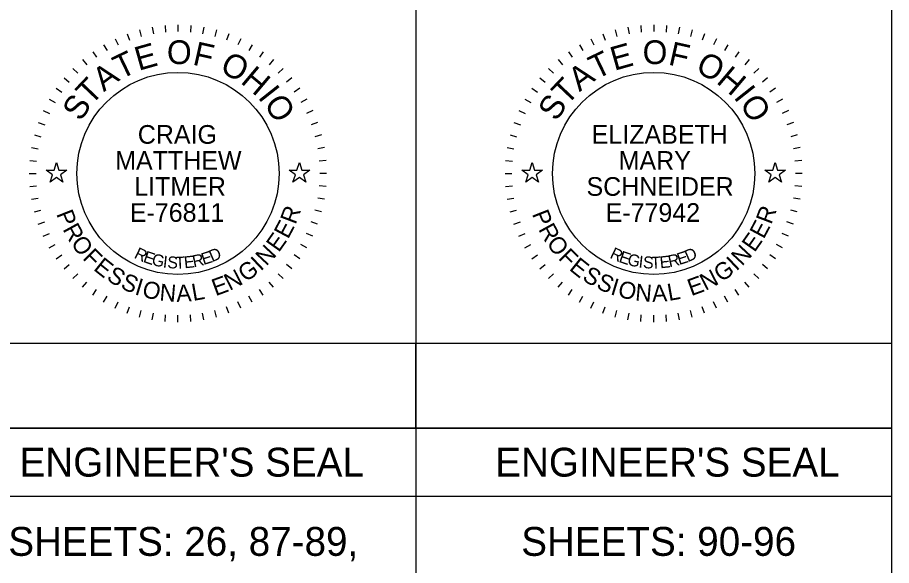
# Model space of a CAD drawing. Extents: x -21.9 to 47.3, y 14.1 to 48.7.
# Drawn here: x 24.06 to 29.2, y 29.92 to 33.15 of the extents above; entities that cross this region are included whole.
import ezdxf

# ---------------------------------------------------------------- set-up
doc = ezdxf.new("R2010")
doc.units = 0
for name, color, linetype in [('SH_Data', 7, 'Continuous'), ('SH_Seal', 7, 'Continuous'), ('SH_Text', 7, 'Continuous')]:
    doc.layers.add(name, color=color, linetype=linetype)

msp = doc.modelspace()

# ---------------------------------------------------------------- linework, layer by layer
at = {"layer": 'SH_Data'}
for p, q in [((26.4, 34.2334), (26.4, 30.7334)), ((29.2, 34.2334), (29.2, 30.7334)), ((23.6, 30.7334), (26.4, 30.7334)), ((23.6, 30.7334), (26.4, 30.7334)), ((26.4, 30.7334), (29.2, 30.7334)), ((26.4, 30.7334), (26.4, 27.2334)), ((26.4, 30.7334), (29.2, 30.7334)), ((29.2, 30.7334), (29.2, 27.2334)), ((23.6, 30.3334), (26.4, 30.3334)), ((26.4, 30.3334), (29.2, 30.3334))]:
    msp.add_line(p, q, dxfattribs=at)
for points in [[(23.6, 30.7334), (23.6, 31.2334), (26.4, 31.2334), (26.4, 30.7334)], [(26.4, 30.7334), (26.4, 31.2334), (29.2, 31.2334), (29.2, 30.7334)]]:
    msp.add_lwpolyline(points, close=True, dxfattribs=at)
at = {"layer": 'SH_Seal'}
for p, q in [((24.8481, 33.0951), (24.855, 33.0557)), ((24.9237, 33.1051), (24.9272, 33.0652)), ((25, 33.1084), (25, 33.0684)), ((25.0763, 33.1051), (25.0728, 33.0652)), ((25.1519, 33.0951), (25.145, 33.0557)), ((27.6481, 33.0951), (27.655, 33.0557)), ((27.7237, 33.1051), (27.7272, 33.0652)), ((27.8, 33.1084), (27.8, 33.0684)), ((27.8763, 33.1051), (27.8728, 33.0652)), ((27.9519, 33.0951), (27.945, 33.0557)), ((24.7007, 33.0556), (24.7144, 33.0181)), ((24.7735, 33.0786), (24.7839, 33.04)), ((25.2265, 33.0786), (25.2161, 33.04)), ((25.2993, 33.0556), (25.2856, 33.0181)), ((27.5007, 33.0556), (27.5144, 33.0181)), ((27.5735, 33.0786), (27.5839, 33.04)), ((28.0265, 33.0786), (28.0161, 33.04)), ((28.0993, 33.0556), (28.0856, 33.0181)), ((24.5625, 32.9912), (24.5825, 32.9565)), ((24.6302, 33.0264), (24.6471, 32.9902)), ((25.3698, 33.0264), (25.3529, 32.9902)), ((25.4375, 32.9912), (25.4175, 32.9565)), ((27.3625, 32.9912), (27.3825, 32.9565)), ((27.4302, 33.0264), (27.4471, 32.9902)), ((28.1698, 33.0264), (28.1529, 32.9902)), ((28.2375, 32.9912), (28.2175, 32.9565)), ((24.4981, 32.9502), (24.5211, 32.9174)), ((25.5019, 32.9502), (25.4789, 32.9174)), ((27.2981, 32.9502), (27.3211, 32.9174)), ((28.3019, 32.9502), (28.2789, 32.9174)), ((24.4376, 32.9037), (24.4633, 32.8731)), ((25.5624, 32.9037), (25.5367, 32.8731)), ((27.2376, 32.9037), (27.2633, 32.8731)), ((28.3624, 32.9037), (28.3367, 32.8731)), ((24.3813, 32.8521), (24.4096, 32.8238)), ((25.6187, 32.8521), (25.5904, 32.8238)), ((27.1813, 32.8521), (27.2096, 32.8238)), ((28.4187, 32.8521), (28.3904, 32.8238)), ((24.3297, 32.7959), (24.3604, 32.7701)), ((25.6703, 32.7959), (25.6396, 32.7701)), ((27.1297, 32.7959), (27.1604, 32.7701)), ((28.4703, 32.7959), (28.4396, 32.7701)), ((24.2832, 32.7353), (24.316, 32.7123)), ((25.7168, 32.7353), (25.684, 32.7123)), ((27.0832, 32.7353), (27.116, 32.7123)), ((28.5168, 32.7353), (28.484, 32.7123)), ((24.2422, 32.6709), (24.2769, 32.6509)), ((25.7578, 32.6709), (25.7231, 32.6509)), ((27.0422, 32.6709), (27.0769, 32.6509)), ((28.5578, 32.6709), (28.5231, 32.6509)), ((24.207, 32.6032), (24.2432, 32.5863)), ((25.793, 32.6032), (25.7568, 32.5863)), ((27.007, 32.6032), (27.0432, 32.5863)), ((28.593, 32.6032), (28.5568, 32.5863)), ((24.1778, 32.5327), (24.2154, 32.519)), ((25.8222, 32.5327), (25.7846, 32.519)), ((26.9778, 32.5327), (27.0154, 32.519)), ((28.6222, 32.5327), (28.5846, 32.519)), ((24.1548, 32.4599), (24.1935, 32.4495)), ((25.8452, 32.4599), (25.8065, 32.4495)), ((26.9548, 32.4599), (26.9935, 32.4495)), ((28.6452, 32.4599), (28.6065, 32.4495)), ((24.1383, 32.3854), (24.1777, 32.3784)), ((25.8617, 32.3854), (25.8223, 32.3784)), ((26.9383, 32.3854), (26.9777, 32.3784)), ((28.6617, 32.3854), (28.6223, 32.3784)), ((24.1283, 32.3097), (24.1682, 32.3062)), ((25.8717, 32.3097), (25.8318, 32.3062)), ((26.9283, 32.3097), (26.9682, 32.3062)), ((28.6717, 32.3097), (28.6318, 32.3062)), ((24.125, 32.2334), (24.165, 32.2334)), ((25.875, 32.2334), (25.835, 32.2334)), ((26.925, 32.2334), (26.965, 32.2334)), ((28.675, 32.2334), (28.635, 32.2334)), ((24.1283, 32.1571), (24.1682, 32.1606)), ((25.8717, 32.1571), (25.8318, 32.1606)), ((26.9283, 32.1571), (26.9682, 32.1606)), ((28.6717, 32.1571), (28.6318, 32.1606)), ((24.1383, 32.0815), (24.1777, 32.0884)), ((25.8617, 32.0815), (25.8223, 32.0884)), ((26.9383, 32.0815), (26.9777, 32.0884)), ((28.6617, 32.0815), (28.6223, 32.0884)), ((24.1548, 32.0069), (24.1935, 32.0173)), ((25.8452, 32.0069), (25.8065, 32.0173)), ((26.9548, 32.0069), (26.9935, 32.0173)), ((28.6452, 32.0069), (28.6065, 32.0173)), ((24.1778, 31.9341), (24.2154, 31.9478)), ((25.8222, 31.9341), (25.7846, 31.9478)), ((26.9778, 31.9341), (27.0154, 31.9478)), ((28.6222, 31.9341), (28.5846, 31.9478)), ((24.207, 31.8636), (24.2432, 31.8805)), ((25.793, 31.8636), (25.7568, 31.8805)), ((27.007, 31.8636), (27.0432, 31.8805)), ((28.593, 31.8636), (28.5568, 31.8805)), ((24.2422, 31.7959), (24.2769, 31.8159)), ((25.7578, 31.7959), (25.7231, 31.8159)), ((27.0422, 31.7959), (27.0769, 31.8159)), ((28.5578, 31.7959), (28.5231, 31.8159)), ((24.2832, 31.7315), (24.316, 31.7545)), ((25.7168, 31.7315), (25.684, 31.7545)), ((27.0832, 31.7315), (27.116, 31.7545)), ((28.5168, 31.7315), (28.484, 31.7545)), ((24.3297, 31.671), (24.3604, 31.6967)), ((25.6703, 31.671), (25.6396, 31.6967)), ((27.1297, 31.671), (27.1604, 31.6967)), ((28.4703, 31.671), (28.4396, 31.6967)), ((24.3813, 31.6147), (24.4096, 31.643)), ((25.6187, 31.6147), (25.5904, 31.643)), ((27.1813, 31.6147), (27.2096, 31.643)), ((28.4187, 31.6147), (28.3904, 31.643)), ((24.4376, 31.5631), (24.4633, 31.5938)), ((25.5624, 31.5631), (25.5367, 31.5938)), ((27.2376, 31.5631), (27.2633, 31.5938)), ((28.3624, 31.5631), (28.3367, 31.5938)), ((24.4981, 31.5167), (24.5211, 31.5494)), ((25.5019, 31.5167), (25.4789, 31.5494)), ((27.2981, 31.5167), (27.3211, 31.5494)), ((28.3019, 31.5167), (28.2789, 31.5494)), ((24.5625, 31.4756), (24.5825, 31.5103)), ((25.4375, 31.4756), (25.4175, 31.5103)), ((27.3625, 31.4756), (27.3825, 31.5103)), ((28.2375, 31.4756), (28.2175, 31.5103)), ((24.6302, 31.4404), (24.6471, 31.4766)), ((24.7007, 31.4112), (24.7144, 31.4488)), ((25.2993, 31.4112), (25.2856, 31.4488)), ((25.3698, 31.4404), (25.3529, 31.4766)), ((27.4302, 31.4404), (27.4471, 31.4766)), ((27.5007, 31.4112), (27.5144, 31.4488)), ((28.0993, 31.4112), (28.0856, 31.4488)), ((28.1698, 31.4404), (28.1529, 31.4766)), ((24.7735, 31.3882), (24.7839, 31.4269)), ((24.8481, 31.3717), (24.855, 31.4111)), ((24.9237, 31.3617), (24.9272, 31.4016)), ((25, 31.3584), (25, 31.3984)), ((25.0763, 31.3617), (25.0728, 31.4016)), ((25.1519, 31.3717), (25.145, 31.4111)), ((25.2265, 31.3882), (25.2161, 31.4269)), ((27.5735, 31.3882), (27.5839, 31.4269)), ((27.6481, 31.3717), (27.655, 31.4111)), ((27.7237, 31.3617), (27.7272, 31.4016)), ((27.8, 31.3584), (27.8, 31.3984)), ((27.8763, 31.3617), (27.8728, 31.4016)), ((27.9519, 31.3717), (27.945, 31.4111)), ((28.0265, 31.3882), (28.0161, 31.4269))]:
    msp.add_line(p, q, dxfattribs=at)
for points in [[(24.2236, 32.2534), (24.2705, 32.2534), (24.285, 32.2979), (24.2995, 32.2534), (24.3464, 32.2534), (24.3085, 32.2258), (24.323, 32.1812), (24.285, 32.2088), (24.247, 32.1812), (24.2615, 32.2258)], [(25.6536, 32.2534), (25.7005, 32.2534), (25.715, 32.2979), (25.7295, 32.2534), (25.7764, 32.2534), (25.7385, 32.2258), (25.753, 32.1812), (25.715, 32.2088), (25.677, 32.1812), (25.6915, 32.2258)], [(27.0236, 32.2534), (27.0705, 32.2534), (27.085, 32.2979), (27.0995, 32.2534), (27.1464, 32.2534), (27.1085, 32.2258), (27.123, 32.1812), (27.085, 32.2088), (27.047, 32.1812), (27.0615, 32.2258)], [(28.4536, 32.2534), (28.5005, 32.2534), (28.515, 32.2979), (28.5295, 32.2534), (28.5764, 32.2534), (28.5385, 32.2258), (28.553, 32.1812), (28.515, 32.2088), (28.477, 32.1812), (28.4915, 32.2258)]]:
    msp.add_lwpolyline(points, close=True, dxfattribs=at)
for centre in [(25, 32.2334), (27.8, 32.2334)]:
    msp.add_circle(centre, 0.595, dxfattribs=at)

# ---------------------------------------------------------------- texts
at = {"layer": 'SH_Data'}
for p in [(24.0676, 30.4484), (26.8676, 30.4484)]:
    msp.add_text("ENGINEER'S SEAL", height=0.17, dxfattribs=at).set_placement(p)
at = {"layer": 'SH_Seal'}
for s, height, rotation, p in [('E', 0.14, 15.7571, (24.7684, 32.8372)), ('O', 0.14, 359.7812, (24.9347, 32.8777)), ('F', 0.14, 347.4362, (25.0811, 32.8751)), ('E', 0.14, 15.7571, (27.5684, 32.8372)), ('O', 0.14, 359.7812, (27.7347, 32.8777)), ('F', 0.14, 347.4362, (27.8811, 32.8751)), ('T', 0.14, 25.7167, (24.6616, 32.7852)), ('O', 0.14, 332.2586, (25.2398, 32.8349)), ('T', 0.14, 25.7167, (27.4616, 32.7852)), ('O', 0.14, 332.2586, (28.0398, 32.8349)), ('A', 0.14, 36.4747, (24.5634, 32.7115)), ('H', 0.14, 319.9136, (25.3632, 32.7695)), ('A', 0.14, 36.4747, (27.3634, 32.7115)), ('H', 0.14, 319.9136, (28.1632, 32.7695)), ('T', 0.14, 46.4344, (24.4883, 32.6299)), ('T', 0.14, 46.4344, (27.2883, 32.6299)), ('I', 0.14, 308.367, (25.4665, 32.6817)), ('I', 0.14, 308.367, (28.2665, 32.6817)), ('S', 0.14, 57.1924, (24.4281, 32.5348)), ('O', 0.14, 303.1491, (25.5021, 32.6423)), ('S', 0.14, 57.1924, (27.2281, 32.5348)), ('O', 0.14, 303.1491, (28.3021, 32.6423)), ('P', 0.1, 291.494, (24.2823, 31.9955)), ('R', 0.1, 69.2322, (25.6919, 31.9288)), ('P', 0.1, 291.494, (27.0823, 31.9955)), ('R', 0.1, 69.2322, (28.4919, 31.9288)), ('E', 0.1, 61.9951, (25.6476, 31.8433)), ('E', 0.1, 61.9951, (28.4476, 31.8433)), ('R', 0.1, 298.7311, (24.319, 31.9051)), ('R', 0.1, 298.7311, (27.119, 31.9051)), ('O', 0.1, 306.4666, (24.3655, 31.8217)), ('E', 0.1, 54.758, (25.5933, 31.7648)), ('O', 0.1, 306.4666, (27.1655, 31.8217)), ('E', 0.1, 54.758, (28.3933, 31.7648)), ('R', 0.07, 334.487, (24.7375, 31.7385)), ('N', 0.1, 47.0224, (25.5202, 31.6842)), ('R', 0.07, 334.487, (27.5375, 31.7385)), ('N', 0.1, 47.0224, (28.3202, 31.6842)), ('F', 0.1, 314.7068, (24.4343, 31.7317)), ('E', 0.07, 341.04, (24.7906, 31.7135)), ('G', 0.07, 347.4752, (24.8414, 31.6952)), ('I', 0.07, 353.7858, (24.9091, 31.6802)), ('S', 0.07, 356.8926, (24.9358, 31.6763)), ('T', 0.07, 3.0061, (24.9857, 31.6721)), ('E', 0.07, 6.0117, (25.0389, 31.6746)), ('R', 0.07, 11.9184, (25.0925, 31.6808)), ('E', 0.07, 17.6836, (25.1498, 31.6936)), ('D', 0.07, 23.3052, (25.201, 31.7104)), ('I', 0.1, 43.287, (25.4868, 31.6548)), ('F', 0.1, 314.7068, (27.2343, 31.7317)), ('E', 0.07, 341.04, (27.5906, 31.7135)), ('G', 0.07, 347.4752, (27.6414, 31.6952)), ('I', 0.07, 353.7858, (27.7091, 31.6802)), ('S', 0.07, 356.8926, (27.7358, 31.6763)), ('T', 0.07, 3.0061, (27.7857, 31.6721)), ('E', 0.07, 6.0117, (27.8389, 31.6746)), ('R', 0.07, 11.9184, (27.8925, 31.6808)), ('E', 0.07, 17.6836, (27.9498, 31.6936)), ('D', 0.07, 23.3052, (28.001, 31.7104)), ('I', 0.1, 43.287, (28.2868, 31.6548)), ('E', 0.1, 321.4393, (24.4978, 31.6682)), ('G', 0.1, 35.0469, (25.3981, 31.5904)), ('E', 0.1, 321.4393, (27.2978, 31.6682)), ('G', 0.1, 35.0469, (28.1981, 31.5904)), ('S', 0.1, 328.6764, (24.5743, 31.6086)), ('S', 0.1, 335.9134, (24.6564, 31.56)), ('N', 0.1, 27.3113, (25.3045, 31.5409)), ('S', 0.1, 328.6764, (27.3743, 31.6086)), ('S', 0.1, 335.9134, (27.4564, 31.56)), ('N', 0.1, 27.3113, (28.1045, 31.5409)), ('I', 0.1, 343.1505, (24.7406, 31.5231)), ('O', 0.1, 346.8859, (24.7839, 31.5085)), ('E', 0.1, 20.0742, (25.2212, 31.5104)), ('I', 0.1, 343.1505, (27.5406, 31.5231)), ('O', 0.1, 346.8859, (27.5839, 31.5085)), ('E', 0.1, 20.0742, (28.0212, 31.5104)), ('N', 0.1, 355.1261, (24.8888, 31.4852)), ('A', 0.1, 2.8617, (24.9923, 31.4771)), ('L', 0.1, 10.0987, (25.0894, 31.4825)), ('N', 0.1, 355.1261, (27.6888, 31.4852)), ('A', 0.1, 2.8617, (27.7923, 31.4771)), ('L', 0.1, 10.0987, (27.8894, 31.4825))]:
    msp.add_text(s, height=height, rotation=rotation, dxfattribs=at).set_placement(p)
for s, p in [('CRAIG ', (24.7635, 32.4083)), ('ELIZABETH', (27.4353, 32.4083)), ('MATTHEW', (24.6304, 32.255)), ('MARY', (27.5938, 32.255)), ('LITMER', (24.7428, 32.1018)), ('SCHNEIDER', (27.4047, 32.1018)), ('E-76811', (24.7167, 31.9485)), ('E-77942', (27.5172, 31.9485))]:
    msp.add_text(s, height=0.11, dxfattribs=at).set_placement(p)
at = {"layer": 'SH_Text'}
for s, p in [('SHEETS: 26, 87-89,', (24.0013, 29.9819)), ('SHEETS: 90-96', (27.0206, 29.9819))]:
    msp.add_text(s, height=0.17, dxfattribs=at).set_placement(p)

doc.saveas('drawing.dxf')
